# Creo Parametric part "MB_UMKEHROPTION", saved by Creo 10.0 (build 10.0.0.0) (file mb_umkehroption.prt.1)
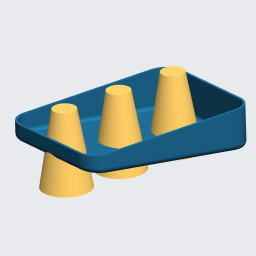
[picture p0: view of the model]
Materials in the file: S235JRG2

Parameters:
  COPY_GEOM_ORIGIN_TYPE = "Part"
  BENENNUNG = "XXX"
  DATUM = "XX.XX.XX"
  ERSTELLER = "ARINDA"
  TEILETYP = "Fertigungsteil"
  PTC_MASTER_MATERIAL = "S235JRG2"
  SELECT_EN_NAME = "S235JRG2"
  SELECT_DIN_NAME = "RSt37-2"
  SELECT_DIN_NUMBER = "1.0038"
  SELECT_ASTM_NAME = "A 283 M Grade 2"
  MATERIAL_GROUP = "ME_ST_Baustahl"
  STANDARD_EN_DELIVERYSPEC = "DIN EN 10025"
  STANDARD_DIN_DELIVERYSPEC = "DIN 17100"

Other parameters: MASSE

Created from: KURVENAUSWAHL.PRT

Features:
  1. coordinate system
  2. datum plane "T_RECHTS_Y-Z"
  3. datum plane "T_OBEN_X-Z"
  4. datum plane "T_VORNE_X-Y"
  5. datum axis
  6. datum axis
  7. datum axis
  8. protrusion
  9. round
  10. feature "Schräge 1"
  11. round "Rundung 2"
  12. revolve "Drehen 1"
  13. shell "Schale 1"
  14. pattern
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
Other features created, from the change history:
  sketch "Skizze 2"
  curve "Kurve 2"
  extrusion "Profil 2"
  datum plane "DTM1" (2 times)
  sketch "Skizze 3"
  revolve "Drehen 1"
  feature "Körper Subtrahieren 1" (5 times)
  feature "Körper Trennen 1" (2 times)
  feature "Kopie-geometrie ID 974"
  feature "Kopie-geometrie ID 990"
  feature "Körper Trimmen 1"
  round "Rundung 2"
  pattern "Muster 2" (2 times)
  feature "Körper Subtrahieren 1 [3]" (2 times)

Other named items: T_BASIC, T_X-ACHSE, T_Y-ACHSE, T_Z-ACHSE

Layers: 00_STD-ACHSEN, 00_STD-EBENEN, 00_STD-KOORDSYS, 01_ACHSEN, 01_EBENEN, 01_KURVEN, KURVENELEMENTE, SAMMELFLÄCHEN, VOLUMENGEOMETRIE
